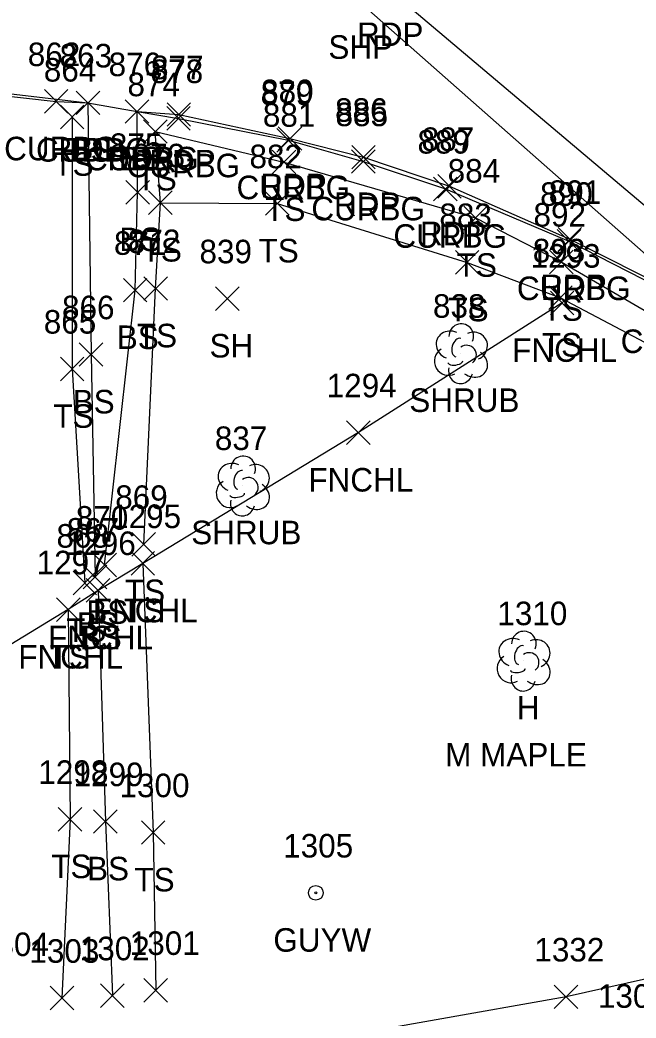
# Model space of a CAD drawing. Extents: x 1688195 to 1692013, y 424605 to 441234.
# Drawn here: x 1691798.5 to 1691850.9, y 439158.5 to 439243.2 of the extents above; entities that cross this region are included whole.
import ezdxf

# ---------------------------------------------------------------- set-up
doc = ezdxf.new("R2010")
doc.units = 0
for name, color, linetype in [('L_A', 7, 'Continuous'), ('L_C', 7, 'Continuous'), ('L_I', 7, 'Continuous'), ('L_TIC', 7, 'Continuous'), ('LELB', 7, 'Continuous'), ('LFNC', 7, 'Continuous'), ('LSH', 7, 'Continuous'), ('LTD', 7, 'Continuous'), ('P_A', 7, 'Continuous'), ('P_I', 7, 'Continuous'), ('P_TIC', 7, 'Continuous'), ('PET', 7, 'Continuous'), ('PSP', 7, 'Continuous'), ('R_A', 7, 'Continuous'), ('R_I', 7, 'Continuous'), ('R_TIC', 7, 'Continuous'), ('RC', 7, 'Continuous'), ('U_A', 7, 'Continuous'), ('U_I', 7, 'Continuous'), ('UPGW', 7, 'Continuous')]:
    doc.layers.add(name, color=color, linetype=linetype)

msp = doc.modelspace()

# ---------------------------------------------------------------- linework, layer by layer
at = {"layer": 'L_TIC'}
for points in [[(1691803.318, 439235.191), (1691805.318, 439237.191)], [(1691805.318, 439235.191), (1691803.318, 439237.191)], [(1691801.972, 439233.992), (1691803.972, 439235.992)], [(1691803.972, 439233.992), (1691801.972, 439235.992)], [(1691807.491, 439234.452), (1691809.491, 439236.452)], [(1691809.491, 439234.452), (1691807.491, 439236.452)], [(1691809.037, 439232.748), (1691811.037, 439234.748)], [(1691811.037, 439232.748), (1691809.037, 439234.748)], [(1691819.977, 439230.155), (1691821.977, 439232.155)], [(1691821.977, 439230.155), (1691819.977, 439232.155)], [(1691807.538, 439227.592), (1691809.538, 439229.592)], [(1691809.538, 439227.592), (1691807.538, 439229.592)], [(1691809.472, 439226.708), (1691811.472, 439228.708)], [(1691811.472, 439226.708), (1691809.472, 439228.708)], [(1691809.472, 439226.708), (1691811.472, 439228.708)], [(1691811.472, 439226.708), (1691809.472, 439228.708)], [(1691819.406, 439226.634), (1691821.406, 439228.634)], [(1691821.406, 439226.634), (1691819.406, 439228.634)], [(1691836.253, 439225.413), (1691838.253, 439227.413)], [(1691838.253, 439225.413), (1691836.253, 439227.413)], [(1691835.548, 439221.635), (1691837.548, 439223.635)], [(1691837.548, 439221.635), (1691835.548, 439223.635)], [(1691843.547, 439221.678), (1691845.547, 439223.678)], [(1691845.547, 439221.678), (1691843.547, 439223.678)], [(1691807.324, 439219.278), (1691809.324, 439221.278)], [(1691809.324, 439219.278), (1691807.324, 439221.278)], [(1691809.068, 439219.423), (1691811.068, 439221.423)], [(1691811.068, 439219.423), (1691809.068, 439221.423)], [(1691815.164, 439218.56), (1691817.164, 439220.56)], [(1691817.164, 439218.56), (1691815.164, 439220.56)], [(1691843.486, 439218.638), (1691845.486, 439220.638)], [(1691845.486, 439218.638), (1691843.486, 439220.638)], [(1691843.629, 439218.191), (1691845.629, 439220.191)], [(1691845.629, 439218.191), (1691843.629, 439220.191)], [(1691803.577, 439213.81), (1691805.577, 439215.81)], [(1691805.577, 439213.81), (1691803.577, 439215.81)], [(1691801.97, 439212.589), (1691803.97, 439214.589)], [(1691803.97, 439212.589), (1691801.97, 439214.589)], [(1691826.301, 439207.177), (1691828.301, 439209.177)], [(1691828.301, 439207.177), (1691826.301, 439209.177)], [(1691808.053, 439197.7), (1691810.053, 439199.7)], [(1691810.053, 439197.7), (1691808.053, 439199.7)], [(1691804.732, 439195.94), (1691806.732, 439197.94)], [(1691806.732, 439195.94), (1691804.732, 439197.94)], [(1691807.981, 439196.073), (1691809.981, 439198.073)], [(1691809.981, 439196.073), (1691807.981, 439198.073)], [(1691807.981, 439196.073), (1691809.981, 439198.073)], [(1691809.981, 439196.073), (1691807.981, 439198.073)], [(1691803.921, 439194.921), (1691805.921, 439196.921)], [(1691805.921, 439194.921), (1691803.921, 439196.921)], [(1691803.053, 439194.412), (1691805.053, 439196.412)], [(1691805.053, 439194.412), (1691803.053, 439196.412)], [(1691804.179, 439193.785), (1691806.179, 439195.785)], [(1691806.179, 439193.785), (1691804.179, 439195.785)], [(1691804.179, 439193.785), (1691806.179, 439195.785)], [(1691806.179, 439193.785), (1691804.179, 439195.785)], [(1691801.646, 439192.147), (1691803.646, 439194.147)], [(1691803.646, 439192.147), (1691801.646, 439194.147)], [(1691801.646, 439192.147), (1691803.646, 439194.147)], [(1691803.646, 439192.147), (1691801.646, 439194.147)], [(1691801.792, 439174.347), (1691803.792, 439176.347)], [(1691803.792, 439174.347), (1691801.792, 439176.347)], [(1691804.798, 439174.156), (1691806.798, 439176.156)], [(1691806.798, 439174.156), (1691804.798, 439176.156)], [(1691808.857, 439173.219), (1691810.857, 439175.219)], [(1691810.857, 439173.219), (1691808.857, 439175.219)], [(1691801.108, 439159.159), (1691803.108, 439161.159)], [(1691803.108, 439159.159), (1691801.108, 439161.159)], [(1691805.391, 439159.37), (1691807.391, 439161.37)], [(1691807.391, 439159.37), (1691805.391, 439161.37)], [(1691809.075, 439159.824), (1691811.075, 439161.824)], [(1691811.075, 439159.824), (1691809.075, 439161.824)], [(1691843.953, 439159.267), (1691845.953, 439161.267)], [(1691845.953, 439159.267), (1691843.953, 439161.267)]]:
    msp.add_lwpolyline(points, dxfattribs=at)
at = {"layer": 'LELB'}
for points in [[(1691804.318, 439236.191), (1691804.577, 439214.81), (1691804.921, 439195.921)], [(1691802.972, 439234.992), (1691802.97, 439213.589), (1691804.053, 439195.412)], [(1691805.732, 439196.94), (1691808.324, 439220.278), (1691808.538, 439228.592), (1691808.491, 439235.452)], [(1691809.053, 439198.7), (1691810.068, 439220.423), (1691810.472, 439227.708), (1691810.037, 439233.748), (1691820.977, 439231.155), (1691837.253, 439226.413), (1691844.547, 439222.678), (1691860.674, 439213.285), (1691879.413, 439197.187), (1691884.864, 439187.773), (1691888.44, 439178.127), (1691882.001, 439154.551), (1691849.25, 439142.61), (1691815.325, 439128.47), (1691761.502, 439106.684), (1691722.867, 439092.032), (1691697.517, 439087.726), (1691657.954, 439070.386), (1691613.621, 439049.579), (1691576.983, 439020.144), (1691544.829, 438993.146), (1691508.196, 438954.885), (1691488.694, 438935.2)], [(1691810.472, 439227.708), (1691820.406, 439227.634), (1691836.548, 439222.635), (1691844.486, 439219.638), (1691859.36, 439211.797), (1691878.234, 439195.791), (1691884.864, 439187.773)], [(1691808.981, 439197.073), (1691809.857, 439174.219), (1691810.075, 439160.824)], [(1691805.179, 439194.785), (1691805.798, 439175.156), (1691806.391, 439160.37)], [(1691802.646, 439193.147), (1691802.792, 439175.347), (1691802.108, 439160.159)], [(1691867.083, 439165.211), (1691844.953, 439160.267), (1691798.836, 439152.108), (1691745.507, 439147.112), (1691728.71, 439142.405), (1691709.094, 439133.879), (1691682.996, 439117.204), (1691643.276, 439091.076), (1691604.891, 439061.286), (1691572.531, 439026.723), (1691542.378, 438995.546), (1691505.845, 438957.496), (1691487.655, 438936.341), (1691466.81, 438915.543), (1691436.023, 438880.856), (1691415.553, 438858.764)]]:
    msp.add_lwpolyline(points, dxfattribs=at)
at = {"layer": 'LFNC'}
msp.add_lwpolyline([(1691844.629, 439219.191), (1691827.301, 439208.177), (1691808.981, 439197.073), (1691805.179, 439194.785), (1691802.646, 439193.147), (1691780.926, 439179.949), (1691740.493, 439155.554), (1691707.63, 439134.904), (1691682.092, 439120.044), (1691638.963, 439093.47), (1691599.841, 439067.337), (1691566.38, 439033.383), (1691536.946, 439001.218), (1691500.893, 438961.261), (1691462.913, 438919.547), (1691429.394, 438883.141), (1691411.257, 438863.122)], dxfattribs=at)
at = {"layer": 'LSH'}
for p, q in [((1691836.002, 439214.936), (1691836.002, 439214.936)), ((1691836.002, 439214.936), (1691836.002, 439214.936)), ((1691817.465, 439203.702), (1691817.465, 439203.702)), ((1691817.465, 439203.702), (1691817.465, 439203.702))]:
    msp.add_line(p, q, dxfattribs=at)
for centre in [(1691836.049, 439216.37), (1691817.511, 439205.136)]:
    msp.add_arc(centre, 1.047, 335.52715, 180.95627, dxfattribs=at)
for centre, major_axis, ratio, start_param, end_param in [((1691835.21, 439215.603), (1.21, -0.512), 0.895232, 1.570796, 4.712389), ((1691835.794, 439215.395), (-0.208, -0.792), 0.645439, 3.141593, 6.283185), ((1691837.044, 439215.52), (-1.141, -0.483), 0.949671, 1.570796, 4.712389), ((1691836.502, 439214.77), (-0.5, 0.667), 0.989748, 3.141593, 6.283185), ((1691834.919, 439214.228), (0.584, -1.042), 0.959034, 3.141593, 6.283185), ((1691837.002, 439214.103), (-1.09, 0.792), 0.841452, 1.570796, 4.712389), ((1691836.002, 439213.436), (0.265, 1.061), 0.942809, 1.570796, 4.712389), ((1691835.544, 439214.186), (-0.625, -0.083), 0.423636, 0, 3.141593), ((1691816.673, 439204.369), (1.21, -0.512), 0.895232, 1.570796, 4.712389), ((1691818.506, 439204.286), (-1.141, -0.483), 0.949671, 1.570796, 4.712389), ((1691817.256, 439204.161), (-0.208, -0.792), 0.645439, 3.141593, 6.283185), ((1691817.965, 439203.536), (-0.5, 0.667), 0.989748, 3.141593, 6.283185), ((1691816.381, 439202.994), (0.584, -1.042), 0.959034, 3.141593, 6.283185), ((1691818.465, 439202.869), (-1.09, 0.792), 0.841452, 1.570796, 4.712389), ((1691817.006, 439202.952), (-0.625, -0.083), 0.423636, 0, 3.141593), ((1691817.465, 439202.202), (0.265, 1.061), 0.942809, 1.570796, 4.712389)]:
    msp.add_ellipse(centre, major_axis=major_axis, ratio=ratio, start_param=start_param, end_param=end_param, dxfattribs=at)
at = {"layer": 'LTD'}
msp.add_line((1691841.327, 439188.827), (1691841.327, 439188.827), dxfattribs=at)
msp.add_line((1691841.327, 439188.827), (1691841.327, 439188.827), dxfattribs=at)
msp.add_arc((1691841.373, 439190.261), 1.047, 335.52715, 180.95627, dxfattribs=at)
for centre, major_axis, ratio, start_param, end_param in [((1691840.535, 439189.494), (1.21, -0.512), 0.895232, 1.570796, 4.712389), ((1691842.368, 439189.411), (-1.141, -0.483), 0.949671, 1.570796, 4.712389), ((1691841.118, 439189.286), (-0.208, -0.792), 0.645439, 3.141593, 6.283185), ((1691840.243, 439188.119), (0.584, -1.042), 0.959034, 3.141593, 6.283185), ((1691841.827, 439188.661), (-0.5, 0.667), 0.989748, 3.141593, 6.283185), ((1691842.327, 439187.994), (-1.09, 0.792), 0.841452, 1.570796, 4.712389), ((1691841.327, 439187.327), (0.265, 1.061), 0.942809, 1.570796, 4.712389), ((1691840.868, 439188.077), (-0.625, -0.083), 0.423636, 0, 3.141593)]:
    msp.add_ellipse(centre, major_axis=major_axis, ratio=ratio, start_param=start_param, end_param=end_param, dxfattribs=at)
at = {"layer": 'P_TIC'}
for points in [[(1691803.318, 439235.191), (1691805.318, 439237.191)], [(1691805.318, 439235.191), (1691803.318, 439237.191)], [(1691807.491, 439234.452), (1691809.491, 439236.452)], [(1691809.491, 439234.452), (1691807.491, 439236.452)], [(1691811.042, 439234.195), (1691813.042, 439236.195)], [(1691813.042, 439234.195), (1691811.042, 439236.195)], [(1691820.483, 439232.162), (1691822.483, 439234.162)], [(1691822.483, 439232.162), (1691820.483, 439234.162)], [(1691826.737, 439230.575), (1691828.737, 439232.575)], [(1691828.737, 439230.575), (1691826.737, 439232.575)], [(1691834.045, 439228.097), (1691836.045, 439230.097)], [(1691836.045, 439228.097), (1691834.045, 439230.097)], [(1691844.28, 439223.601), (1691846.28, 439225.601)], [(1691846.28, 439223.601), (1691844.28, 439225.601)]]:
    msp.add_lwpolyline(points, dxfattribs=at)
at = {"layer": 'PET'}
for points in [[(1691703.519, 439378.215), (1691727.927, 439348.964), (1691752.514, 439320.765), (1691774.827, 439296.788), (1691803.993, 439267.935), (1691829.698, 439246.009), (1691860.192, 439220.256)], [(1691715.714, 439221.672), (1691737.082, 439230.055), (1691750.128, 439233.775), (1691763.328, 439236.221), (1691779.804, 439237.901), (1691792.46, 439237.573), (1691804.318, 439236.191), (1691808.491, 439235.452), (1691812.042, 439235.195), (1691821.483, 439233.162), (1691827.737, 439231.575), (1691835.045, 439229.097), (1691845.28, 439224.601), (1691854.138, 439220.168), (1691861.506, 439215.423), (1691883.06, 439199.579), (1691888.13, 439193.66), (1691894.204, 439181.616), (1691894.95, 439171.633), (1691892.497, 439160.46), (1691888.634, 439152.728)]]:
    msp.add_lwpolyline(points, dxfattribs=at)
at = {"layer": 'PSP'}
msp.add_lwpolyline([(1691696.132, 439372.686), (1691709.548, 439355.191), (1691723.603, 439339.325), (1691742.747, 439319), (1691750.974, 439309.526), (1691763.384, 439297.713), (1691773.94, 439286.942), (1691807.317, 439260.152), (1691827.219, 439244.924), (1691853.912, 439221.372)], dxfattribs=at)
at = {"layer": 'R_TIC'}
for points in [[(1691800.61, 439235.306), (1691802.61, 439237.306)], [(1691802.61, 439235.306), (1691800.61, 439237.306)], [(1691803.318, 439235.191), (1691805.318, 439237.191)], [(1691805.318, 439235.191), (1691803.318, 439237.191)], [(1691807.491, 439234.452), (1691809.491, 439236.452)], [(1691809.491, 439234.452), (1691807.491, 439236.452)], [(1691811.009, 439233.868), (1691813.009, 439235.868)], [(1691813.009, 439233.868), (1691811.009, 439235.868)], [(1691820.363, 439232.003), (1691822.363, 439234.003)], [(1691822.363, 439232.003), (1691820.363, 439234.003)], [(1691826.722, 439230.205), (1691828.722, 439232.205)], [(1691828.722, 439230.205), (1691826.722, 439232.205)], [(1691833.697, 439227.878), (1691835.697, 439229.878)], [(1691835.697, 439227.878), (1691833.697, 439229.878)], [(1691844.197, 439223.436), (1691846.197, 439225.436)], [(1691846.197, 439223.436), (1691844.197, 439225.436)]]:
    msp.add_lwpolyline(points, dxfattribs=at)
at = {"layer": 'RC'}
for points in [[(1691673.648, 439189.009), (1691697.785, 439210.208), (1691710.111, 439217.785), (1691716.003, 439221.174), (1691737.358, 439229.742), (1691750.141, 439233.54), (1691763.412, 439236.009), (1691779.913, 439237.569), (1691792.753, 439237.293), (1691801.61, 439236.306), (1691804.318, 439236.191)], [(1691808.491, 439235.452), (1691812.009, 439234.868), (1691821.363, 439233.003), (1691827.722, 439231.205), (1691834.697, 439228.878), (1691845.197, 439224.436), (1691854.015, 439219.94), (1691861.435, 439215.191), (1691881.097, 439200.869), (1691883.06, 439199.579)]]:
    msp.add_lwpolyline(points, dxfattribs=at)
at = {"layer": 'UPGW'}
for radius in [0.625, 0.0833]:
    msp.add_circle((1691823.683, 439169.097), radius, dxfattribs=at)

# ---------------------------------------------------------------- texts
at = {"layer": 'L_A'}
for s, p in [('BS', (1691802.759, 439231.191)), ('BS', (1691806.931, 439230.452)), ('TS', (1691801.382, 439229.992)), ('TS', (1691808.447, 439228.748)), ('TS', (1691819.386, 439226.155)), ('BS', (1691806.979, 439223.592)), ('TS', (1691808.881, 439222.708)), ('TS', (1691808.881, 439222.708)), ('TS', (1691818.816, 439222.634)), ('TS', (1691835.662, 439221.413)), ('TS', (1691834.957, 439217.635)), ('TS', (1691842.956, 439217.678)), ('BS', (1691806.765, 439215.278)), ('TS', (1691808.477, 439215.423)), ('SH', (1691814.652, 439214.56)), ('FNCHL', (1691840.377, 439214.191)), ('TS', (1691842.896, 439214.638)), ('SHRUB', (1691831.632, 439209.936)), ('BS', (1691803.018, 439209.81)), ('TS', (1691801.38, 439208.589)), ('FNCHL', (1691823.049, 439203.177)), ('SHRUB', (1691813.095, 439198.702)), ('TS', (1691807.462, 439193.7)), ('BS', (1691804.173, 439191.94)), ('FNCHL', (1691804.729, 439192.073)), ('TS', (1691807.391, 439192.073)), ('TS', (1691802.463, 439190.412)), ('BS', (1691803.362, 439190.921)), ('FNCHL', (1691800.927, 439189.785)), ('BS', (1691803.62, 439189.785)), ('FNCHL', (1691798.394, 439188.147)), ('TS', (1691801.055, 439188.147)), ('H', (1691840.76, 439183.827)), ('TS', (1691801.201, 439170.347)), ('BS', (1691804.239, 439170.156)), ('TS', (1691808.267, 439169.219))]:
    msp.add_text(s, height=2, dxfattribs=at).set_placement(p)
at = {"layer": 'L_C'}
msp.add_text('M MAPLE', height=2, dxfattribs=at).set_placement((1691834.681, 439179.827))
at = {"layer": 'L_I'}
for s, p in [('863', (1691801.909, 439239.191)), ('864', (1691800.563, 439237.992)), ('876', (1691806.073, 439238.452)), ('874', (1691807.675, 439236.748)), ('881', (1691819.182, 439234.155)), ('875', (1691806.176, 439231.592)), ('873', (1691808.11, 439230.708)), ('873', (1691808.11, 439230.708)), ('882', (1691818.044, 439230.634)), ('884', (1691834.891, 439229.413)), ('883', (1691834.185, 439225.635)), ('892', (1691842.185, 439225.678)), ('871', (1691806.529, 439223.278)), ('872', (1691807.705, 439223.423)), ('893', (1691842.124, 439222.638)), ('839', (1691813.794, 439222.56)), ('1293', (1691841.936, 439222.191)), ('866', (1691802.112, 439217.81)), ('838', (1691833.64, 439217.936)), ('865', (1691800.561, 439216.589)), ('1294', (1691824.608, 439211.177)), ('837', (1691815.102, 439206.702)), ('869', (1691806.635, 439201.7)), ('870', (1691803.283, 439199.94)), ('1295', (1691806.288, 439200.073)), ('1295', (1691806.288, 439200.073)), ('867', (1691802.511, 439198.921)), ('868', (1691801.644, 439198.412)), ('1296', (1691802.431, 439197.785)), ('1296', (1691802.431, 439197.785)), ('1297', (1691799.953, 439196.147)), ('1297', (1691799.953, 439196.147)), ('1310', (1691839.114, 439191.827)), ('1298', (1691800.099, 439178.347)), ('1299', (1691803.097, 439178.156)), ('1300', (1691806.999, 439177.219)), ('1302', (1691803.619, 439163.37)), ('1301', (1691807.871, 439163.824)), ('1332', (1691842.26, 439163.267)), ('1303', (1691799.337, 439163.159))]:
    msp.add_text(s, height=2, dxfattribs=at).set_placement(p)
at = {"layer": 'P_A'}
for s, p in [('RDP', (1691827.186, 439241.009)), ('SHP', (1691824.754, 439239.924)), ('RDP', (1691801.806, 439231.191)), ('RDP', (1691805.979, 439230.452)), ('RDP', (1691809.53, 439230.195)), ('RDP', (1691818.972, 439228.162)), ('RDP', (1691825.225, 439226.575)), ('RDP', (1691832.534, 439224.097)), ('RDP', (1691842.768, 439219.601))]:
    msp.add_text(s, height=2, dxfattribs=at).set_placement(p)
at = {"layer": 'P_I'}
for s, p in [('863', (1691801.909, 439239.191)), ('876', (1691806.073, 439238.452)), ('877', (1691809.68, 439238.195)), ('880', (1691819.035, 439236.162)), ('886', (1691825.32, 439234.575)), ('887', (1691832.683, 439232.097)), ('891', (1691843.484, 439227.601))]:
    msp.add_text(s, height=2, dxfattribs=at).set_placement(p)
at = {"layer": 'R_A'}
for p in [(1691797.193, 439231.306), (1691799.901, 439231.191), (1691804.073, 439230.452), (1691807.591, 439229.868), (1691816.945, 439228.003), (1691823.305, 439226.205), (1691830.28, 439223.878), (1691840.78, 439219.436), (1691849.598, 439214.94)]:
    msp.add_text('CURBG', height=2, dxfattribs=at).set_placement(p)
at = {"layer": 'R_I'}
for s, p in [('862', (1691799.201, 439239.306)), ('863', (1691801.909, 439239.191)), ('876', (1691806.073, 439238.452)), ('878', (1691809.647, 439237.868)), ('879', (1691818.993, 439236.003)), ('885', (1691825.36, 439234.205)), ('889', (1691832.327, 439231.878)), ('890', (1691842.748, 439227.436))]:
    msp.add_text(s, height=2, dxfattribs=at).set_placement(p)
at = {"layer": 'U_A'}
msp.add_text('GUYW', height=2, dxfattribs=at).set_placement((1691820.076, 439164.097))
at = {"layer": 'U_I'}
for s, p in [('1305', (1691820.911, 439172.097)), ('1304', (1691795.056, 439163.728)), ('1306', (1691847.661, 439159.336))]:
    msp.add_text(s, height=2, dxfattribs=at).set_placement(p)

doc.saveas('drawing.dxf')
